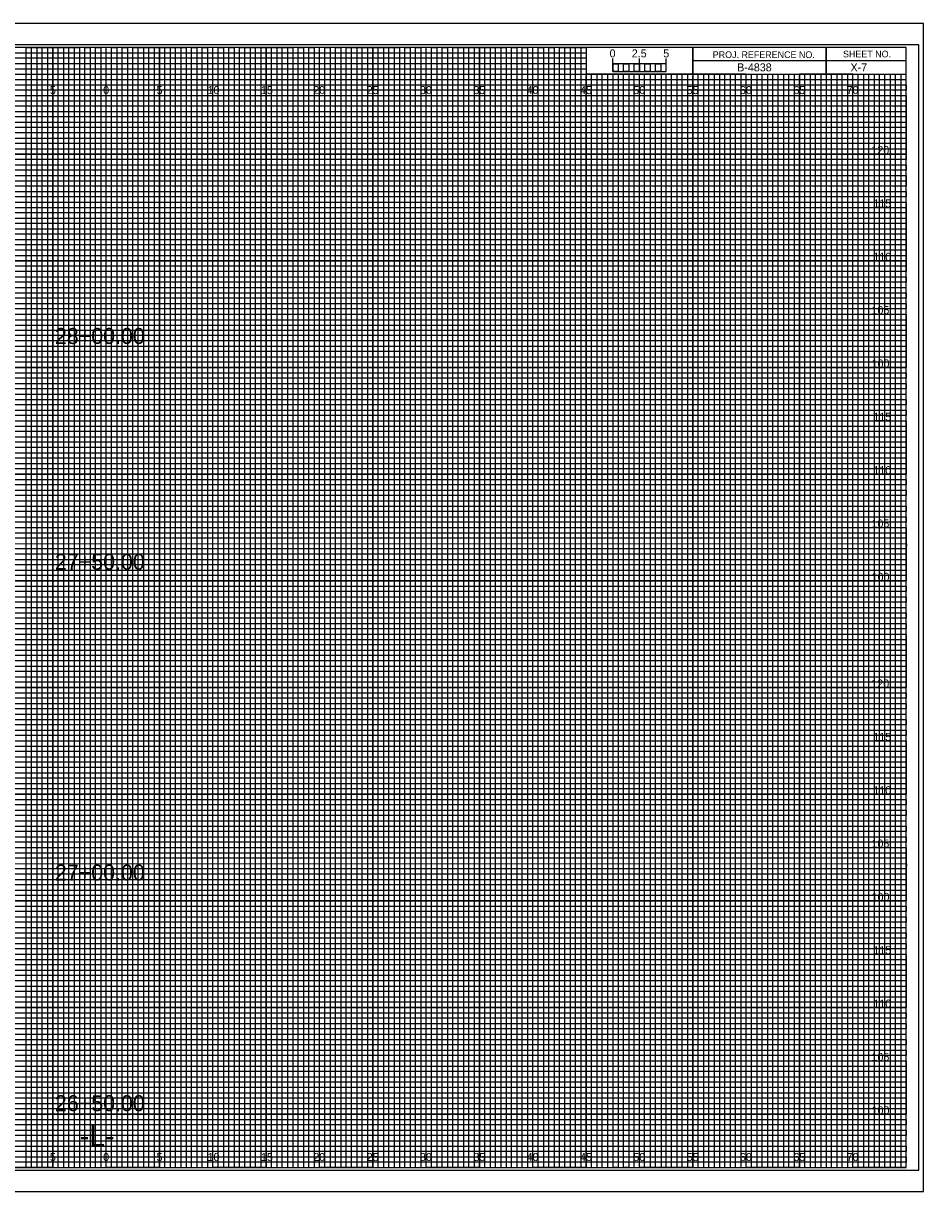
# Model space of a CAD drawing. Extents: x -7 to 182, y -2 to 1647.
# Drawn here: x 77.2 to 161.7, y 547.8 to 657.2 of the extents above; entities that cross this region are included whole.
import ezdxf

# ---------------------------------------------------------------- set-up
doc = ezdxf.new("R2010")
doc.units = 0
for name, color, linetype in [('Exist CMT Pavement', 7, 'Continuous'), ('Exist Cross Section Cell', 7, 'Continuous'), ('Exist XS Ground Line', 7, 'Continuous'), ('Prop CMT Pvmt Course 1', 7, 'Continuous'), ('Prop CMT Pvmt Course 2', 7, 'Continuous'), ('Prop CMT Pvmt Course 2 Wedge', 7, 'Continuous'), ('Prop CMT Pvmt Course 3', 7, 'Continuous'), ('Prop CMT Pvmt Surface', 7, 'Continuous'), ('Prop CMT Pvmt Surface Shoulder', 7, 'Continuous'), ('Prop CMT Pvmt Wedge Surface 1', 7, 'Continuous'), ('Prop CMT Pvmt Wedge Surface 2', 7, 'Continuous'), ('Prop CMT Pvmt Wedge Surface 3', 7, 'Continuous'), ('Prop CMT Shld Paved Course 1', 7, 'Continuous'), ('Prop CMT Shld Paved Course 2', 7, 'Continuous'), ('Prop CMT Shld Paved Course 3', 7, 'Continuous'), ('Prop CMT Slope Grass', 7, 'Continuous'), ('Prop CMT Subgrade Earthwork', 7, 'Continuous')]:
    doc.layers.add(name, color=color, linetype=linetype)

msp = doc.modelspace()

# ---------------------------------------------------------------- linework, layer by layer
at = {"layer": 'Exist XS Ground Line'}
for p, q in [((85, 655), (80, 655)), ((80, 655), (80, 550)), ((85, 550), (85, 655)), ((95, 655), (90, 655)), ((90, 655), (90, 550)), ((95, 550), (95, 655)), ((105, 655), (100, 655)), ((100, 655), (100, 550)), ((105, 550), (105, 655)), ((115, 655), (110, 655)), ((110, 655), (110, 550)), ((115, 550), (115, 655)), ((125, 655), (120, 655)), ((120, 655), (120, 550)), ((125, 550), (125, 655)), ((130, 655), (130, 550)), ((135, 550), (135, 652.5)), ((145, 652.5), (140, 652.5)), ((140, 652.5), (140, 550)), ((145, 550), (145, 652.5)), ((155, 652.5), (150, 652.5)), ((150, 652.5), (150, 550)), ((155, 550), (155, 652.5)), ((80, 550), (75, 550)), ((90, 550), (85, 550)), ((100, 550), (95, 550)), ((110, 550), (105, 550)), ((120, 550), (115, 550)), ((130, 550), (125, 550)), ((140, 550), (135, 550)), ((150, 550), (145, 550)), ((160, 550), (155, 550)), ((160, 550), (160, 550))]:
    msp.add_line(p, q, dxfattribs=at)
for points in [[(0, 650), (160, 650), (160, 645), (0, 645)], [(0, 640), (160, 640), (160, 635), (0, 635)], [(0, 630), (160, 630), (160, 625), (0, 625)], [(0, 620), (160, 620), (160, 615), (0, 615)], [(0, 610), (160, 610), (160, 605), (0, 605)], [(0, 600), (160, 600), (160, 595), (0, 595)], [(0, 590), (160, 590), (160, 585), (0, 585)], [(0, 580), (160, 580), (160, 575), (0, 575)], [(0, 570), (160, 570), (160, 565), (0, 565)], [(0, 560), (160, 560), (160, 555), (0, 555)]]:
    msp.add_lwpolyline(points, dxfattribs=at)
at = {"layer": 'Prop CMT Pvmt Course 2'}
for p, q in [((132.5, 652.75), (132.5, 653.95)), ((132.5, 653.45), (132.5, 653.95)), ((135, 652.75), (135, 653.95)), ((137.5, 652.75), (137.5, 653.95)), ((137.5, 653.45), (137.5, 653.95))]:
    msp.add_line(p, q, dxfattribs=at)
for points in [[(137.5, 653.45), (132.5, 653.45), (132.5, 652.75), (137.5, 652.75)], [(132.5, 653.45), (133, 653.45), (133, 652.75), (132.5, 652.75)], [(133.5, 653.45), (134, 653.45), (134, 652.75), (133.5, 652.75)], [(134.5, 653.45), (135, 653.45), (135, 652.75), (134.5, 652.75)], [(135.5, 653.45), (136, 653.45), (136, 652.75), (135.5, 652.75)], [(136.5, 653.45), (137, 653.45), (137, 652.75), (136.5, 652.75)]]:
    msp.add_lwpolyline(points, close=True, dxfattribs=at)
at = {"layer": 'Prop CMT Pvmt Course 3'}
msp.add_lwpolyline([(-6.7, 547.75), (161.65, 547.75), (161.65, 657.25), (-6.7, 657.25)], close=True, dxfattribs=at)
at = {"layer": 'Prop CMT Pvmt Wedge Surface 1'}
for p, q in [((0, 654.5), (130, 654.5)), ((130, 653.99), (0, 653.99)), ((130, 654.5), (130, 653.99)), ((0, 653.5), (130, 653.5)), ((130, 652.95), (0, 652.95)), ((130, 653.5), (130, 652.95)), ((0, 652), (160, 652))]:
    msp.add_line(p, q, dxfattribs=at)
for points in [[(0, 651.5), (135, 651.5), (160, 651.5), (160, 651), (0, 651)], [(0, 650.5), (160, 650.5), (160, 649.5), (0, 649.5)], [(0, 649), (160, 649), (160, 648.5), (0, 648.49)], [(0, 648), (160, 648), (160, 647), (0, 647)], [(0, 646.5), (160, 646.5), (160, 646), (0, 646)], [(0, 645.5), (160, 645.5), (160, 644.5), (0, 644.5)], [(0, 644), (160, 644), (160, 643.5), (0, 643.5)], [(0, 643), (160, 643), (160, 642), (0, 642)], [(0, 641.5), (160, 641.5), (160, 641), (0, 641)], [(0, 640.5), (160, 640.5), (160, 639.5), (0, 639.5)], [(0, 639), (160, 639), (160, 638.5), (0, 638.5)], [(0, 638), (160, 638), (160, 636.98), (160, 636.5), (160, 636), (0, 636)], [(0, 637), (160, 637), (160, 636.5), (0, 636.5)], [(0, 635.5), (160, 635.5), (160, 634.5), (0, 634.51)], [(0, 634.51), (160, 634.5), (160, 634), (0, 634)], [(0, 633.5), (160, 633.5), (160, 633), (0, 633)], [(0, 632), (160, 632), (160, 631.5), (0, 631.5)], [(0, 631), (160, 631), (160, 630.5), (0, 630.5)], [(-0.04, 629.45), (160, 629.45), (160, 628.94), (-0.04, 628.94)], [(0, 628.5), (160, 628.5), (160, 628), (0, 628)], [(0, 627), (160, 627), (160, 626.5), (0, 626.5)], [(0, 626), (160, 626), (160, 625.5), (0, 625.5)], [(0, 624.5), (160, 624.5), (160, 624), (0, 624)], [(0, 623.5), (160, 623.5), (160, 623), (0, 623)], [(0, 622), (160, 622), (160, 621.5), (0, 621.5)], [(0, 621), (160, 621), (160, 620.5), (0, 620.5)], [(0, 619.5), (160, 619.5), (160, 618.99), (0, 619)], [(0, 618.5), (160, 618.5), (160, 618), (0, 618)], [(0, 617), (160, 617), (160, 616.5), (0, 616.5)], [(0, 616), (160, 616), (160, 615.5), (0, 615.5)], [(0, 614.5), (160, 614.5), (160, 614), (0, 614)], [(0, 613.5), (160, 613.5), (160, 613), (0, 613)], [(0, 612), (160, 612), (160, 611.5), (0, 611.5)], [(0, 611), (160, 611), (160, 610.5), (0, 610.5)], [(0, 609.5), (160, 609.5), (160, 609), (0, 609)], [(0, 608.5), (160.03, 608.46), (160, 608), (0, 608)], [(0, 607), (160, 607), (160, 606.5), (0, 606.5)], [(0, 606), (160, 606), (160, 605.5), (0, 605.5)], [(0, 604.5), (160, 604.5), (160, 604), (0, 604)], [(0, 603.5), (160, 603.5), (160, 603), (0, 603)], [(0, 602), (160, 602), (160, 601.5), (0, 601.5)], [(0, 601), (160, 601), (160, 600.5), (0, 600.5)], [(0, 599.5), (160, 599.5), (160, 599), (0, 599)], [(0, 598.5), (160, 598.5), (160, 598), (0, 598)], [(0, 597), (160, 597), (160, 596.5), (0, 596.5)], [(0, 596), (160, 596), (160, 595.5), (0, 595.5)], [(0, 594.5), (160, 594.5), (160, 594), (0, 594)], [(0, 593.5), (160, 593.5), (160, 593), (0, 593)], [(0, 592), (160, 592), (160, 591.5), (0, 591.5)], [(0, 591), (160, 591), (160, 590.5), (0, 590.5)], [(0, 589.5), (160, 589.5), (160, 588.99), (0, 589)], [(0, 588.5), (160, 588.5), (160, 588), (0, 588)], [(0, 587), (160, 587), (160, 586.5), (0, 586.5)], [(0, 586), (160, 586), (160, 585.5), (0, 585.5)], [(0, 584.5), (160, 584.5), (160, 584), (0, 584)], [(0, 583.5), (160, 583.5), (160, 583), (0, 583)], [(0, 582), (160, 582), (160, 581.5), (0, 581.5)], [(0, 581), (160, 581), (160, 580.5), (0, 580.5)], [(0, 579.5), (160, 579.5), (160, 579), (0, 579)], [(0, 578.5), (160.03, 578.46), (160, 578), (0, 578)], [(0, 577), (160, 577), (160, 576.5), (0, 576.5)], [(0, 576), (160, 576), (160, 575.5), (0, 575.5)], [(0, 574.5), (160, 574.5), (160, 574), (0, 574)], [(0, 573.5), (160, 573.5), (160, 573), (0, 573)], [(0, 572), (160, 572), (160, 571.5), (0, 571.5)], [(0, 571), (160, 571), (160, 570.5), (0, 570.5)], [(0, 569.5), (160, 569.5), (160, 569), (0, 569)], [(0, 568.5), (160, 568.5), (160, 568), (0, 568)], [(0, 567), (160, 567), (160, 566.5), (0, 566.5)], [(0, 566), (160, 566), (160, 565.5), (0, 565.5)], [(0, 564.5), (160, 564.5), (160, 564), (0, 564)], [(0, 563.5), (160, 563.5), (160, 563), (0, 563)], [(0, 562), (160, 562), (160, 561.5), (0, 561.5)], [(0, 561), (160, 561), (160, 560.5), (0, 560.5)], [(0, 559.5), (160, 559.5), (160, 559), (0, 559)], [(0, 558.5), (160, 558.5), (160, 558), (0, 558)], [(0, 557), (160, 557), (160, 556.5), (0, 556.5)], [(0, 556), (160, 556), (160, 555.5), (0, 555.5)], [(0, 554.5), (160, 554.5), (160, 554), (0, 554)], [(0, 553.5), (160, 553.5), (160, 553), (0, 553)], [(0, 552), (160, 552), (160, 551.5), (0, 551.5)], [(0, 551), (160, 551), (160, 550.5), (0, 550.5)]]:
    msp.add_lwpolyline(points, dxfattribs=at)
at = {"layer": 'Prop CMT Pvmt Wedge Surface 2'}
for p, q in [((152.5, 655), (152.5, 652.5)), ((152.5, 652.5), (152.5, 655)), ((160, 653.75), (140, 653.75)), ((140, 653.75), (140, 652.5)), ((140, 652.5), (160, 652.5))]:
    msp.add_line(p, q, dxfattribs=at)
for points in [[(160, 655), (0, 655), (0, 550), (160, 550)], [(140, 655), (130, 655), (130, 652.51), (140, 652.51)], [(160, 655), (140, 655), (140, 652.5), (160, 652.5)]]:
    msp.add_lwpolyline(points, close=True, dxfattribs=at)
at = {"layer": 'Prop CMT Pvmt Wedge Surface 3'}
for p, q in [((133.5, 652.5), (133, 652.5)), ((133, 652.5), (133, 550)), ((133.5, 550), (133.5, 652.5)), ((134.5, 652.5), (134, 652.5)), ((134, 652.5), (134, 550)), ((134.5, 550), (134.5, 652.5)), ((133, 550), (132.5, 550)), ((134, 550), (133.5, 550))]:
    msp.add_line(p, q, dxfattribs=at)
for points in [[(77.5, 550), (78, 550), (78, 655), (78.5, 655), (78.5, 550)], [(78.5, 550), (79, 550), (79, 655), (79.5, 655), (79.5, 550)], [(80, 550), (80.5, 550), (80.5, 655), (81, 655), (81, 550)], [(81, 550), (81.5, 550), (81.5, 655), (82, 655), (82, 550)], [(82.5, 550), (83, 550), (83, 655), (83.5, 655), (83.5, 550)], [(83.5, 550), (84, 550), (84, 655), (84.5, 655), (84.5, 550)], [(85, 550), (85.5, 550), (85.5, 655), (86, 655), (86, 550)], [(86, 550), (86.5, 550), (86.5, 655), (87, 655), (87, 550)], [(87.5, 550), (88, 550), (88, 655), (88.5, 655), (88.5, 550)], [(88.5, 550), (89, 550), (89, 655), (89.5, 655), (89.5, 550)], [(90, 550), (90.5, 550), (90.5, 655), (91, 655), (91, 550)], [(91, 550), (91.5, 550), (91.5, 655), (92, 655), (92, 550)], [(92.5, 550), (93, 550), (93, 655), (93.5, 655), (93.5, 550)], [(93.5, 550), (94, 550), (94, 655), (94.5, 655), (94.5, 550)], [(95, 550), (95.5, 550), (95.5, 655), (96, 655), (96, 550)], [(96, 550), (96.5, 550), (96.5, 655), (97, 655), (97, 550)], [(97.5, 550), (98, 550), (98, 655), (98.5, 655), (98.5, 550)], [(98.5, 550), (99, 550), (99, 655), (99.5, 655), (99.5, 550)], [(100, 550), (100.5, 550), (100.5, 655), (101, 655), (101, 550)], [(101, 550), (101.5, 550), (101.5, 655), (102, 655), (102, 550)], [(102.5, 550), (103, 550), (103, 655), (103.5, 655), (103.5, 550)], [(103.5, 550), (104, 550), (104, 655), (104.5, 655), (104.5, 550)], [(105, 550), (105.5, 550), (105.5, 655), (106, 655), (106, 550)], [(106, 550), (106.5, 550), (106.5, 655), (107, 655), (107, 550)], [(107.5, 550), (108, 550), (108, 655), (108.5, 655), (108.5, 550)], [(108.5, 550), (109, 550), (109, 655), (109.5, 655), (109.5, 550)], [(110, 550), (110.5, 550), (110.5, 655), (111, 655), (111, 550)], [(111, 550), (111.5, 550), (111.5, 655), (112, 655), (112, 550)], [(112.5, 550), (113, 550), (113, 655), (113.5, 655), (113.5, 550)], [(113.5, 550), (114, 550), (114, 655), (114.5, 655), (114.5, 550)], [(115, 550), (115.5, 550), (115.5, 655), (116, 655), (116, 550)], [(116, 550), (116.5, 550), (116.5, 655), (117, 655), (117, 550)], [(117.5, 550), (118, 550), (118, 655), (118.5, 655), (118.5, 550)], [(118.5, 550), (119, 550), (119, 655), (119.5, 655), (119.5, 550)], [(120, 550), (120.5, 550), (120.5, 655), (121, 655), (121, 550)], [(121, 550), (121.5, 550), (121.5, 655), (122, 655), (122, 550)], [(122.5, 550), (123, 550), (123, 655), (123.5, 655), (123.5, 550)], [(123.5, 550), (124, 550), (124, 655), (124.5, 655), (124.5, 550)], [(125, 550), (125.5, 550), (125.5, 655), (126, 655), (126, 550)], [(126, 550), (126.5, 550), (126.5, 655), (127, 655), (127, 550)], [(127.5, 550), (128, 550), (128, 655), (128.5, 655), (128.5, 550)], [(128.5, 550), (129, 550), (129, 655), (129.5, 655), (129.5, 550)], [(130, 550), (130.5, 550), (130.5, 652.5), (131.01, 652.5), (131.01, 550)], [(131, 550), (131.5, 550), (131.5, 652.5), (132, 652.5), (132, 550)], [(135, 550), (135.49, 550), (135.49, 652.5), (136, 652.5), (136, 550)], [(136, 550), (136.5, 550), (136.5, 652.5), (137.03, 652.5), (137.03, 550)], [(137.5, 550), (138, 550), (138, 652.5), (138.5, 652.5), (138.5, 550)], [(138.5, 550), (139, 550), (139, 652.5), (139.5, 652.5), (139.5, 550)], [(140, 550), (140.5, 550), (140.5, 652.5), (141, 652.5), (141, 550)], [(141, 550), (141.5, 550), (141.5, 652.5), (142, 652.5), (142, 550)], [(142.5, 550), (143, 550), (143, 652.5), (143.5, 652.5), (143.5, 550)], [(143.5, 550), (144, 550), (144, 652.5), (144.5, 652.5), (144.5, 550)], [(145, 550), (145.5, 550), (145.5, 652.5), (146, 652.5), (146, 550)], [(146, 550), (146.5, 550), (146.5, 652.5), (147, 652.5), (147, 550)], [(147.5, 550), (148, 550), (148, 652.5), (148.5, 652.5), (148.5, 550)], [(148.5, 550), (149, 550), (149, 652.5), (149.5, 652.5), (149.5, 550)], [(150, 550), (150.5, 550), (150.5, 652.5), (151, 652.5), (151, 550)], [(151, 550), (151.5, 550), (151.5, 652.5), (152, 652.5), (152, 550)], [(152.5, 550), (153, 550), (153, 652.5), (153.5, 652.5), (153.5, 550)], [(153.5, 550), (154, 550), (154, 652.5), (154.5, 652.5), (154.5, 550)], [(155, 550), (155.5, 550), (155.5, 652.5), (156, 652.5), (156, 550)], [(156, 550), (156.5, 550), (156.5, 652.5), (157, 652.5), (157, 550)], [(157.5, 550), (158, 550), (158, 652.5), (158.5, 652.5), (158.5, 550)], [(158.5, 550), (159, 550), (159, 652.5), (159.5, 652.5), (159.5, 550)]]:
    msp.add_lwpolyline(points, dxfattribs=at)
at = {"layer": 'Prop CMT Shld Paved Course 1'}
for p, q in [((80, 550), (80, 655)), ((85, 550), (85, 655)), ((90, 550), (90, 655)), ((95, 550), (95, 655)), ((100, 550), (100, 655)), ((105, 550), (105, 655)), ((110, 550), (110, 655)), ((115, 550), (115, 655)), ((120, 550), (120, 655)), ((125, 550), (125, 655)), ((130, 550), (130, 652.34)), ((135, 550), (135, 652.34)), ((140, 550), (140, 652.34)), ((145, 550), (145, 652.34)), ((150, 550), (150, 652.34)), ((155, 550), (155, 652.34)), ((0, 650), (160, 650)), ((0, 645), (160, 645)), ((0, 640), (160, 640)), ((0, 635), (160, 635)), ((0, 630), (160, 630)), ((0, 625), (160, 625)), ((0, 620), (160, 620)), ((0, 615), (160, 615)), ((0, 610), (160, 610)), ((0, 605), (160, 605)), ((0, 600), (160, 600)), ((0, 595), (160, 595)), ((0, 590), (160, 590)), ((0, 585), (160, 585)), ((0, 580), (160, 580)), ((0, 575), (160, 575)), ((0, 570), (160, 570)), ((0, 565), (160, 565)), ((0, 560), (160, 560)), ((0, 555), (160, 555))]:
    msp.add_line(p, q, dxfattribs=at)
at = {"layer": 'Prop CMT Shld Paved Course 2'}
for p, q in [((161.65, 657.25), (-6.7, 657.25)), ((-6.7, 547.75), (161.65, 547.75))]:
    msp.add_line(p, q, dxfattribs=at)
at = {"layer": 'Prop CMT Slope Grass'}
msp.add_lwpolyline([(-5.4, 549.75), (161.2, 549.75), (161.2, 655.25), (-5.4, 655.25)], close=True, dxfattribs=at)
at = {"layer": 'Prop CMT Subgrade Earthwork'}
for points in [[(72.5, 550), (77.5, 550), (77.5, 655), (82.5, 655), (82.5, 550), (87.5, 550), (87.5, 655), (92.5, 655), (92.5, 550), (97.5, 550), (97.5, 655), (102.5, 655), (102.5, 550), (107.5, 550), (107.5, 655), (112.5, 655), (112.5, 550), (117.5, 550), (117.5, 655), (122.5, 655), (122.5, 550), (127.5, 550), (127.5, 655), (129.97, 655), (130, 655), (130, 652.5), (132.5, 652.5), (132.5, 550), (137.5, 550), (137.5, 652.5), (142.5, 652.5), (142.5, 550), (147.5, 550), (147.5, 652.5), (152.5, 652.5), (152.5, 550), (157.5, 550), (157.5, 652.5)], [(0, 652.5), (137.5, 652.5)], [(0, 642.5), (160, 642.5), (160, 647.5), (0, 647.5)], [(0, 632.5), (160, 632.5), (160, 637.5), (0, 637.5)], [(0, 622.5), (160, 622.5), (160, 627.5), (0, 627.5)], [(0, 612.5), (160, 612.5), (160, 617.5), (0, 617.5)], [(0, 602.5), (160, 602.5), (160, 607.5), (0, 607.5)], [(0, 592.5), (160, 592.5), (160, 597.5), (0, 597.5)], [(0, 582.5), (160, 582.5), (160, 587.5), (0, 587.5)], [(0, 572.5), (160, 572.5), (160, 577.5), (0, 577.5)], [(0, 562.5), (160, 562.5), (160, 567.5), (0, 567.5)], [(0, 552.5), (160, 552.5), (160, 557.5), (0, 557.5)]]:
    msp.add_lwpolyline(points, dxfattribs=at)

# ---------------------------------------------------------------- texts
at = {"layer": 'Exist CMT Pavement'}
for s, p in [('28+00.00', (80.21, 627.2)), ('27+50.00', (80.21, 606.04)), ('27+00.00', (80.21, 576.91)), ('26+50.00', (80.21, 555.29))]:
    msp.add_text(s, height=1.5, dxfattribs=at).set_placement(p)
at = {"layer": 'Exist Cross Section Cell'}
for s, p in [('5', (79.74, 650.62)), ('0', (84.73, 650.62)), ('0', (84.73, 650.62)), ('5', (89.74, 650.62)), ('10', (94.52, 650.62)), ('15', (99.53, 650.62)), ('20', (104.43, 650.62)), ('25', (109.44, 650.62)), ('30', (114.43, 650.62)), ('35', (119.44, 650.62)), ('40', (124.43, 650.62)), ('45', (129.44, 650.62)), ('50', (134.43, 650.62)), ('55', (139.44, 650.62)), ('60', (144.43, 650.62)), ('65', (149.44, 650.62)), ('70', (154.43, 650.62)), ('5', (79.74, 550.62)), ('0', (84.73, 550.62)), ('0', (84.73, 550.62)), ('5', (89.74, 550.62)), ('10', (94.52, 550.62)), ('15', (99.53, 550.62)), ('20', (104.43, 550.62)), ('25', (109.44, 550.62)), ('30', (114.43, 550.62)), ('35', (119.44, 550.62)), ('40', (124.43, 550.62)), ('45', (129.44, 550.62)), ('50', (134.43, 550.62)), ('55', (139.44, 550.62)), ('60', (144.43, 550.62)), ('65', (149.44, 550.62)), ('70', (154.43, 550.62))]:
    msp.add_text(s, height=0.75, dxfattribs=at).set_placement(p)
at = {"layer": 'Prop CMT Pvmt Course 1'}
msp.add_text('-L-', height=2, dxfattribs=at).set_placement((82.53, 552))
at = {"layer": 'Prop CMT Pvmt Course 2'}
msp.add_text('0', height=0.75, dxfattribs=at).set_placement((132.21, 654.06))
at = {"layer": 'Prop CMT Pvmt Course 2 Wedge'}
for s, p in [('2.5', (134.29, 654.06)), ('5', (137.24, 654.06))]:
    msp.add_text(s, height=0.75, dxfattribs=at).set_placement(p)
at = {"layer": 'Prop CMT Pvmt Surface'}
msp.add_text('X-7', height=0.75, dxfattribs=at).set_placement((154.79, 652.75))
at = {"layer": 'Prop CMT Pvmt Surface Shoulder'}
msp.add_text('B-4838', height=0.75, dxfattribs=at).set_placement((144.17, 652.75))
at = {"layer": 'Prop CMT Pvmt Wedge Surface 2'}
for s, p in [('PROJ. REFERENCE NO.', (141.88, 654)), ('SHEET NO.', (154.09, 654.06))]:
    msp.add_text(s, height=0.625, dxfattribs=at).set_placement(p)
at = {"layer": 'Prop CMT Shld Paved Course 3'}
for s, p in [('120', (156.75, 645)), ('115', (156.93, 640)), ('110', (156.94, 635)), ('105', (156.76, 630)), ('100', (156.77, 625)), ('115', (156.93, 620)), ('110', (156.94, 615)), ('105', (156.76, 610)), ('100', (156.77, 605)), ('120', (156.75, 595)), ('115', (156.93, 590)), ('110', (156.94, 585)), ('105', (156.76, 580)), ('100', (156.77, 575)), ('115', (156.93, 570)), ('110', (156.94, 565)), ('105', (156.76, 560)), ('100', (156.77, 555))]:
    msp.add_text(s, height=0.75, dxfattribs=at).set_placement(p)

doc.saveas('drawing.dxf')
